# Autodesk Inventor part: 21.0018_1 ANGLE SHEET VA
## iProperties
Created: 2012-11
Part Number: 21.0018_1 ANGLE SHEET VA
Document SubType Name: Modeling
Designer: Administrator
Density: 8.08 g/cm^3
Material: Stainless Steel
Mass: 165.69 g
Surface Area: 106.086 cm^2
Volume: 20.5062 cm^3
Author: Administrator
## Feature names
1. Extrusion1
2. Extrusion2
3. Fillet1
4. Hole1
